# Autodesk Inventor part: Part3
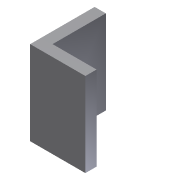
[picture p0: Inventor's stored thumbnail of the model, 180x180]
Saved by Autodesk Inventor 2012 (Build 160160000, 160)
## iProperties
Created: 2009-05
Part Number: Part3
Document SubType Name: Modeling
Designer: Sham
Density: 1 g/cm^3
Material: Default
Author: Sham
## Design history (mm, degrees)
sketch "Sketch1"
  geometry: L1 (-20, 23)-(-20, 0); L2 (-20, 0)-(-0.309, 0); L3 (-0.309, 0)-(-0.309, 4); L4 (-0.309, 4)-(-16, 4); L5 (-16, 4)-(-16, 23); L6 (-16, 23)-(-20, 23)
  constraints: 12 end point, 5 perpendicular
extrude "Extrusion1" new body sketch "Sketch1" distance "d0" = 30; taper "d1" = 0 deg
body "Solid1"
